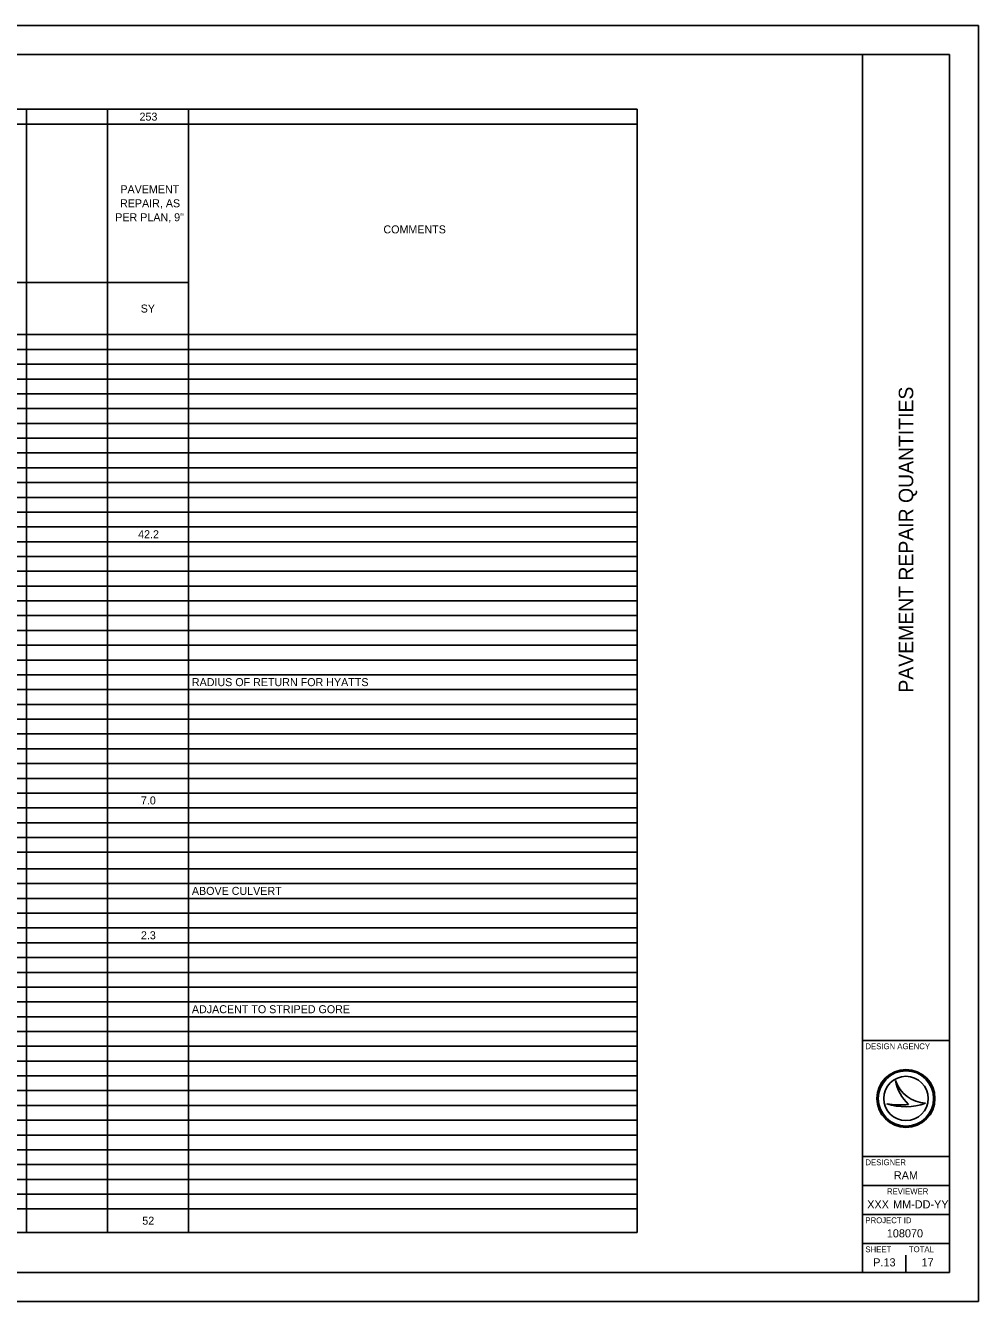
# Model space of a CAD drawing. Extents: x 0 to 34, y 0 to 22.
# Drawn here: x 17.57 to 34, y 0 to 22 of the extents above; entities that cross this region are included whole.
import ezdxf

# ---------------------------------------------------------------- set-up
doc = ezdxf.new("R2010")
doc.units = 0
for name, color, linetype in [('SH_Border', 7, 'Continuous'), ('SH_Cut_Line', 7, 'Continuous'), ('SH_Data', 7, 'Continuous'), ('SH_Text', 7, 'Continuous')]:
    doc.layers.add(name, color=color, linetype=linetype)

msp = doc.modelspace()

# ---------------------------------------------------------------- linework, layer by layer
at = {"layer": 'SH_Border'}
for p, q in [((32, 0.5), (32, 21.5)), ((32, 4.5), (33.5, 4.5)), ((32, 2.5), (33.5, 2.5)), ((32, 2), (33.5, 2)), ((32, 1.5), (33.5, 1.5)), ((32, 1), (33.5, 1))]:
    msp.add_line(p, q, dxfattribs=at)
msp.add_lwpolyline([(1.5, 21.5), (33.5, 21.5), (33.5, 0.5), (1.5, 0.5)], close=True, dxfattribs=at)
at = {"layer": 'SH_Cut_Line'}
msp.add_lwpolyline([(0, 0), (34, 0), (34, 22), (0, 22)], close=True, dxfattribs=at)
at = {"layer": 'SH_Data'}
for p, q in [((32.567, 3.81), (32.567, 3.81)), ((32.417, 3.41), (32.417, 3.41)), ((32.75, 3.5), (32.75, 3.5)), ((33.087, 3.419), (33.087, 3.419)), ((32.375, 0.675), (32.375, 0.675)), ((32.75, 0.5), (32.75, 0.8))]:
    msp.add_line(p, q, dxfattribs=at)
for radius in [0.5, 0.477, 0.477, 0.382]:
    msp.add_circle((32.75, 3.5), radius, dxfattribs=at)
for centre, radius, start, end in [((33.116, 3.998), 0.58, 198.9257, 198.9319), ((33.347, 3.97), 0.796, 191.6379, 191.6421), ((33.116, 3.998), 0.58, 198.9319, 267.1657), ((33.347, 3.97), 0.796, 191.6421, 226.0947), ((32.739, 4.37), 1.013, 251.4576, 290.0832), ((32.648, 4.654), 1.266, 259.4964, 259.4995), ((32.739, 4.37), 1.013, 251.4527, 251.4576), ((32.648, 4.654), 1.266, 259.4995, 276.6672)]:
    msp.add_arc(centre, radius, start, end, dxfattribs=at)
at = {"layer": 'SH_Text'}
for p, q in [((6.051, 20.555), (28.116, 20.555)), ((17.586, 20.555), (17.586, 1.19)), ((18.981, 20.555), (18.981, 1.19)), ((20.376, 20.555), (20.376, 1.19)), ((28.116, 20.555), (28.116, 1.19)), ((6.051, 20.3), (28.116, 20.3)), ((12.216, 17.57), (20.376, 17.57)), ((6.051, 16.67), (28.116, 16.67)), ((6.051, 16.415), (28.116, 16.415)), ((6.051, 16.16), (28.116, 16.16)), ((6.051, 15.905), (28.116, 15.905)), ((6.051, 15.65), (28.116, 15.65)), ((6.051, 15.395), (28.116, 15.395)), ((6.051, 15.14), (28.116, 15.14)), ((6.051, 14.885), (28.116, 14.885)), ((6.051, 14.63), (28.116, 14.63)), ((6.051, 14.375), (28.116, 14.375)), ((6.051, 14.12), (28.116, 14.12)), ((6.051, 13.865), (28.116, 13.865)), ((6.051, 13.61), (28.116, 13.61)), ((6.051, 13.355), (28.116, 13.355)), ((6.051, 13.1), (28.116, 13.1)), ((6.051, 12.845), (28.116, 12.845)), ((6.051, 12.59), (28.116, 12.59)), ((6.051, 12.335), (28.116, 12.335)), ((6.051, 12.08), (28.116, 12.08)), ((6.051, 11.825), (28.116, 11.825)), ((6.051, 11.57), (28.116, 11.57)), ((6.051, 11.315), (28.116, 11.315)), ((6.051, 11.06), (28.116, 11.06)), ((6.051, 10.805), (28.116, 10.805)), ((6.051, 10.55), (28.116, 10.55)), ((6.051, 10.295), (28.116, 10.295)), ((6.051, 10.04), (28.116, 10.04)), ((6.051, 9.785), (28.116, 9.785)), ((6.051, 9.53), (28.116, 9.53)), ((6.051, 9.275), (28.116, 9.275)), ((6.051, 9.02), (28.116, 9.02)), ((6.051, 8.765), (28.116, 8.765)), ((6.051, 8.51), (28.116, 8.51)), ((6.051, 8.255), (28.116, 8.255)), ((6.051, 8), (28.116, 8)), ((6.051, 7.745), (28.116, 7.745)), ((6.051, 7.46), (28.116, 7.46)), ((6.051, 7.205), (28.116, 7.205)), ((6.051, 6.95), (28.116, 6.95)), ((6.051, 6.695), (28.116, 6.695)), ((6.051, 6.44), (28.116, 6.44)), ((6.051, 6.185), (28.116, 6.185)), ((6.051, 5.93), (28.116, 5.93)), ((6.051, 5.675), (28.116, 5.675)), ((6.051, 5.42), (28.116, 5.42)), ((6.051, 5.165), (28.116, 5.165)), ((6.051, 4.91), (28.116, 4.91)), ((6.051, 4.655), (28.116, 4.655)), ((6.051, 4.4), (28.116, 4.4)), ((6.051, 4.145), (28.116, 4.145)), ((6.051, 3.89), (28.116, 3.89)), ((6.051, 3.635), (28.116, 3.635)), ((6.051, 3.38), (28.116, 3.38)), ((6.051, 3.125), (28.116, 3.125)), ((6.051, 2.87), (28.116, 2.87)), ((6.051, 2.615), (28.116, 2.615)), ((6.051, 2.36), (28.116, 2.36)), ((6.051, 2.105), (28.116, 2.105)), ((6.051, 1.85), (28.116, 1.85)), ((6.051, 1.595), (28.116, 1.595)), ((6.051, 1.19), (28.116, 1.19))]:
    msp.add_line(p, q, dxfattribs=at)
for points in [[(20.376, 12.845), (28.116, 12.845), (28.116, 12.59), (20.376, 12.59)], [(20.376, 12.08), (28.116, 12.08), (28.116, 11.825), (20.376, 11.825)], [(17.586, 11.825), (18.981, 11.825), (18.981, 11.57), (17.586, 11.57)], [(18.981, 11.825), (20.376, 11.825), (20.376, 11.57), (18.981, 11.57)], [(20.376, 11.825), (28.116, 11.825), (28.116, 11.57), (20.376, 11.57)], [(20.376, 11.57), (28.116, 11.57), (28.116, 11.315), (20.376, 11.315)], [(17.586, 11.315), (18.981, 11.315), (18.981, 11.06), (17.586, 11.06)], [(18.981, 11.315), (20.376, 11.315), (20.376, 11.06), (18.981, 11.06)], [(20.376, 11.315), (28.116, 11.315), (28.116, 11.06), (20.376, 11.06)], [(20.376, 11.06), (28.116, 11.06), (28.116, 10.805), (20.376, 10.805)], [(20.376, 10.805), (28.116, 10.805), (28.116, 10.55), (20.376, 10.55)], [(20.376, 10.55), (28.116, 10.55), (28.116, 10.295), (20.376, 10.295)], [(20.376, 10.295), (28.116, 10.295), (28.116, 10.04), (20.376, 10.04)], [(20.376, 10.04), (28.116, 10.04), (28.116, 9.785), (20.376, 9.785)], [(20.376, 9.785), (28.116, 9.785), (28.116, 9.53), (20.376, 9.53)], [(20.376, 9.53), (28.116, 9.53), (28.116, 9.275), (20.376, 9.275)], [(20.376, 9.02), (28.116, 9.02), (28.116, 8.765), (20.376, 8.765)], [(20.376, 8.765), (28.116, 8.765), (28.116, 8.51), (20.376, 8.51)], [(20.376, 8.51), (28.116, 8.51), (28.116, 8.255), (20.376, 8.255)], [(20.376, 8.255), (28.116, 8.255), (28.116, 8), (20.376, 8)], [(20.376, 8), (28.116, 8), (28.116, 7.745), (20.376, 7.745)], [(20.376, 7.745), (28.116, 7.745), (28.116, 7.46), (20.376, 7.46)], [(20.376, 6.95), (28.116, 6.95), (28.116, 6.695), (20.376, 6.695)], [(20.376, 6.695), (28.116, 6.695), (28.116, 6.44), (20.376, 6.44)], [(20.376, 6.44), (28.116, 6.44), (28.116, 6.185), (20.376, 6.185)], [(20.376, 6.185), (28.116, 6.185), (28.116, 5.93), (20.376, 5.93)], [(20.376, 5.93), (28.116, 5.93), (28.116, 5.675), (20.376, 5.675)], [(20.376, 5.675), (28.116, 5.675), (28.116, 5.42), (20.376, 5.42)], [(20.376, 5.42), (28.116, 5.42), (28.116, 5.165), (20.376, 5.165)], [(20.376, 5.165), (28.116, 5.165), (28.116, 4.91), (20.376, 4.91)], [(17.586, 4.655), (18.981, 4.655), (18.981, 4.4), (17.586, 4.4)], [(18.981, 4.655), (20.376, 4.655), (20.376, 4.4), (18.981, 4.4)], [(20.376, 4.655), (28.116, 4.655), (28.116, 4.4), (20.376, 4.4)], [(20.376, 4.4), (28.116, 4.4), (28.116, 4.145), (20.376, 4.145)]]:
    msp.add_lwpolyline(points, close=True, dxfattribs=at)

# ---------------------------------------------------------------- texts
at = {"layer": 'SH_Data'}
msp.add_text('PAVEMENT REPAIR QUANTITIES', height=0.25, rotation=90, dxfattribs=at).set_placement((32.875, 10.498))
for s, height, p in [('DESIGN AGENCY', 0.1, (32.05, 4.35)), ('DESIGNER', 0.1, (32.05, 2.35)), ('RAM', 0.14, (32.541, 2.105)), ('REVIEWER', 0.1, (32.422, 1.85)), ('XXX', 0.14, (32.081, 1.605)), ('MM-DD-YY', 0.14, (32.527, 1.605)), ('PROJECT ID', 0.1, (32.05, 1.35)), ('108070', 0.14, (32.419, 1.105)), ('SHEET', 0.1, (32.05, 0.85)), ('TOTAL', 0.1, (32.8, 0.85)), ('P.13', 0.14, (32.185, 0.605)), ('17', 0.14, (33.018, 0.605))]:
    msp.add_text(s, height=height, dxfattribs=at).set_placement(p)
at = {"layer": 'SH_Text'}
for s, p in [('253', (19.533, 20.36)), ('PAVEMENT ', (19.203, 19.108)), ('REPAIR, AS ', (19.197, 18.866)), ('PER PLAN, 9"', (19.115, 18.625)), ('COMMENTS', (23.739, 18.416)), ('SY', (19.553, 17.051)), ('42.2', (19.509, 13.16)), ('RADIUS OF RETURN FOR HYATTS', (20.436, 10.61)), ('7.0', (19.557, 8.57)), ('ABOVE CULVERT', (20.436, 7.01)), ('2.3', (19.557, 6.245)), ('ADJACENT TO STRIPED GORE', (20.436, 4.97)), ('52', (19.581, 1.324))]:
    msp.add_text(s, height=0.138, dxfattribs=at).set_placement(p)

doc.saveas('drawing.dxf')
